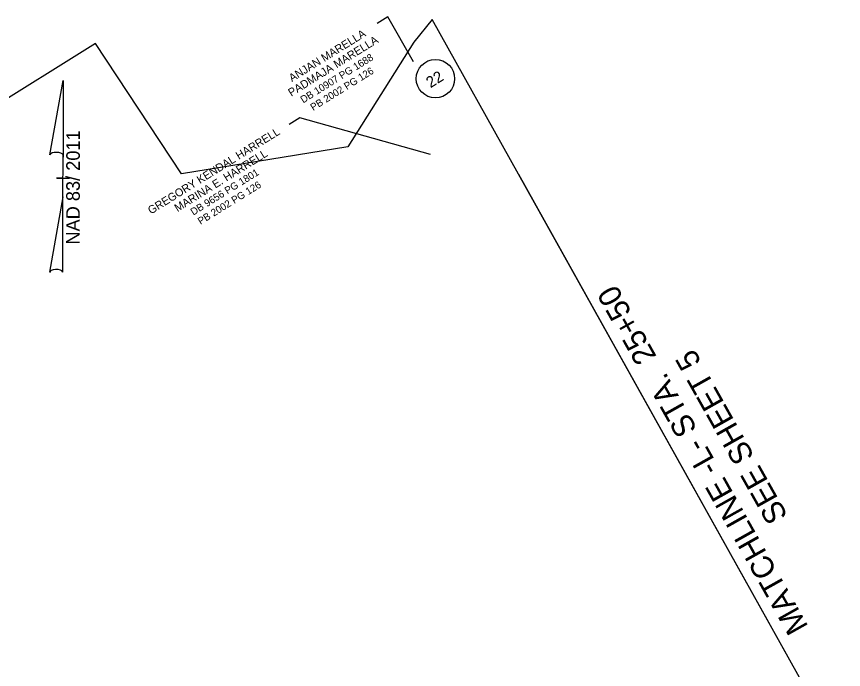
# Model space of a CAD drawing. Extents: x 2045918 to 2047994, y 757573 to 759227.
# Drawn here: x 2046954 to 2047471, y 758615 to 759023 of the extents above; entities that cross this region are included whole.
import ezdxf

# ---------------------------------------------------------------- set-up
doc = ezdxf.new("R2010")
doc.units = 0
for name, color, linetype in [('Default', 7, 'Continuous'), ('Exist Property Deed Book Text', 7, 'Continuous'), ('Exist Property Line Leader', 7, 'Continuous'), ('Exist Property Owner Text', 7, 'Continuous'), ('Matchline', 7, 'Continuous'), ('Matchline Text', 7, 'Continuous'), ('Prop North Arrow NAD83 for Plan Sheets CELL', 7, 'Continuous'), ('Sheet Clip Boundary CELL', 7, 'Continuous')]:
    doc.layers.add(name, color=color, linetype=linetype)

msp = doc.modelspace()

# ---------------------------------------------------------------- linework, layer by layer
at = {"layer": 'Default'}
msp.add_line((2047215.92, 758984), (2047215.92, 758984), dxfattribs=at)
msp.add_circle((2047215.92, 758984), 12, dxfattribs=at)
at = {"layer": 'Exist Property Line Leader'}
for points in [[(2047202.25, 758994.47), (2047186.19, 759022.65), (2047179.55, 759018.47)], [(2047212.89, 758936.54), (2047131.28, 758959.51), (2047124.64, 758955.33)]]:
    msp.add_lwpolyline(points, dxfattribs=at)
at = {"layer": 'Matchline'}
msp.add_line((2047267.81, 758924.31), (2047434.99, 758624.72), dxfattribs=at)
at = {"layer": 'Prop North Arrow NAD83 for Plan Sheets CELL'}
for p, q in [((2046975.09, 758936.52), (2046983.34, 758982.86)), ((2046983.39, 758982.86), (2046983.34, 758982.86)), ((2046983.39, 758982.86), (2046983.34, 758982.86)), ((2046983.39, 758982.86), (2046983.34, 758935.06)), ((2046983.32, 758910.26), (2046983.34, 758936.46)), ((2046983.34, 758935.06), (2046983.34, 758936.41)), ((2046979.33, 758921.87), (2046979.28, 758921.87)), ((2046982.88, 758921.86), (2046979.33, 758921.87)), ((2046979.38, 758921.87), (2046987.38, 758921.86)), ((2046983.32, 758910.26), (2046974.92, 758863.02)), ((2046983.32, 758863.21), (2046983.32, 758910.26))]:
    msp.add_line(p, q, dxfattribs=at)
for centre, start_param, end_param in [((2046979.23, 758936.02), 0.216388, 2.908219), ((2046979.15, 758862.85), 0.201328, 3.141593)]:
    msp.add_ellipse(centre, major_axis=(4.23, -0.03), ratio=0.461098, start_param=start_param, end_param=end_param, dxfattribs=at)
at = {"layer": 'Sheet Clip Boundary CELL'}
msp.add_lwpolyline([(2045946.27, 758464.5), (2046501.43, 757573.22), (2047629.6, 758275.98), (2047267.81, 758924.31), (2047213.84, 759021.02), (2047202.47, 759006.89), (2047161.28, 758941.52), (2047057.27, 758924.6), (2047003.58, 759005.94), (2046934.17, 758962.7), (2046881.6, 759047.1)], close=True, dxfattribs=at)

# ---------------------------------------------------------------- texts
at = {"layer": 'Default'}
msp.add_text('22', height=7, rotation=31.918, dxfattribs=at).set_placement((2047212.83, 758977.96))
at = {"layer": 'Exist Property Deed Book Text'}
for s, rotation, p in [('DB 10907 PG 1688', 31.9183, (2047133.33, 758968.53)), ('PB 2002 PG 126', 31.9183, (2047139.54, 758963.79)), ('DB 9656 PG 1801', 31.9109, (2047064.71, 758898.41)), ('PB 2002 PG 126', 31.9109, (2047069.23, 758892.61))]:
    msp.add_text(s, height=4.5, rotation=rotation, dxfattribs=at).set_placement(p)
at = {"layer": 'Exist Property Owner Text'}
for s, rotation, p in [('ANJAN MARELLA', 31.9183, (2047126.31, 758981.78)), ('PADMAJA MARELLA', 31.9183, (2047125.87, 758972.67)), ('GREGORY KENDAL HARRELL', 31.9109, (2047038.27, 758899.09)), ('MARINA E. HARRELL', 31.9109, (2047054.84, 758900.57))]:
    msp.add_text(s, height=5, rotation=rotation, dxfattribs=at).set_placement(p)
at = {"layer": 'Matchline Text'}
for s, p in [('MATCHLINE -L- STA.  25+50', (2047449.04, 758641.67)), ('SEE SHEET 5', (2047436.3, 758710.8))]:
    msp.add_text(s, height=14, rotation=119.3259, dxfattribs=at).set_placement(p)
at = {"layer": 'Prop North Arrow NAD83 for Plan Sheets CELL'}
msp.add_text('NAD 83/ 2011', height=8.5, rotation=89.9391, dxfattribs=at).set_placement((2046993.8, 758880.33))

doc.saveas('drawing.dxf')
